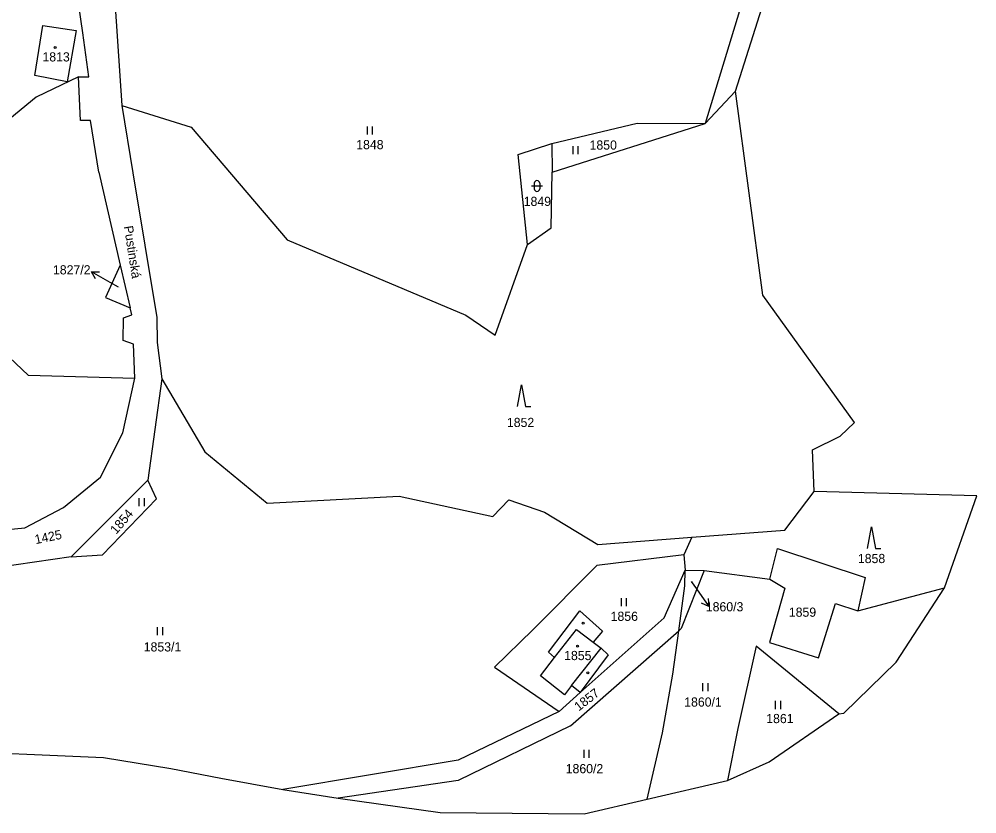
# Model space of a CAD drawing. Extents: x -670359 to -668019, y -978807 to -976674.
# Drawn here: x -668901.2 to -668723.8, y -978807.1 to -978659.9 of the extents above; entities that cross this region are included whole.
import ezdxf

# ---------------------------------------------------------------- set-up
doc = ezdxf.new("R2010")
doc.units = 0
for name, color, linetype in [('Hranice kat_území', 7, 'Continuous'), ('Hranice parcel', 7, 'Continuous'), ('Parcelní čísla', 7, 'Continuous'), ('Pop  PČ popisy', 7, 'Continuous'), ('Vnitřní kresba', 7, 'Continuous'), ('Značky budov', 7, 'Continuous'), ('Značky kultur', 7, 'Continuous')]:
    doc.layers.add(name, color=color, linetype=linetype)

msp = doc.modelspace()

# ---------------------------------------------------------------- linework, layer by layer
at = {"layer": 'Hranice kat_území'}
for points in [[(-668768.5, -978673.25), (-668761.14, -978650.02)], [(-668763.39, -978711.01), (-668768.5, -978673.25)], [(-668746.43, -978734.59), (-668763.39, -978711.01)], [(-668749.12, -978737.1), (-668746.43, -978734.59)], [(-668754.21, -978739.65), (-668749.12, -978737.1)], [(-668753.94, -978747.34), (-668754.21, -978739.65)], [(-668723.78, -978748.19), (-668753.94, -978747.34)], [(-668729.78, -978765.21), (-668723.78, -978748.19)], [(-668738.74, -978778.99), (-668729.78, -978765.21)], [(-668748.42, -978788.44), (-668738.74, -978778.99)], [(-668762.25, -978797.43), (-668749.37, -978788.54)], [(-668749.37, -978788.54), (-668748.42, -978788.44)], [(-668916.93, -978795.26), (-668885.55, -978796.6)], [(-668885.55, -978796.6), (-668873.05, -978798.68)], [(-668769.99, -978800.89), (-668762.25, -978797.43)], [(-668873.05, -978798.68), (-668863.83, -978800.48)], [(-668863.83, -978800.48), (-668852.3, -978802.56)], [(-668784.84, -978804.34), (-668769.99, -978800.89)], [(-668852.3, -978802.56), (-668842.08, -978804.18)], [(-668842.08, -978804.18), (-668823.16, -978806.83)], [(-668796.51, -978807.06), (-668784.84, -978804.34)], [(-668823.16, -978806.83), (-668796.51, -978807.06)]]:
    msp.add_lwpolyline(points, dxfattribs=at)
at = {"layer": 'Hranice parcel'}
for points in [[(-668765.31, -978650.35), (-668774.13, -978679.23)], [(-668889.34, -978662.4), (-668890.13, -978657.34)], [(-668883.41, -978657.54), (-668882.13, -978675.88)], [(-668898.28, -978670.32), (-668896.76, -978661.07)], [(-668896.76, -978661.07), (-668890.61, -978661.98)], [(-668890.61, -978661.98), (-668892.3, -978671.47)], [(-668888.28, -978670.58), (-668889.34, -978662.4)], [(-668892.3, -978671.47), (-668898.28, -978670.32)], [(-668890.2, -978670.54), (-668898.03, -978674.32)], [(-668889.78, -978678.63), (-668890.2, -978670.54)], [(-668890.2, -978670.54), (-668888.28, -978670.58)], [(-668774.13, -978679.23), (-668768.5, -978673.25)], [(-668898.03, -978674.32), (-668902.9, -978678.32)], [(-668882.13, -978675.88), (-668880.1, -978688.32)], [(-668882.13, -978675.88), (-668869.31, -978679.87)], [(-668887.94, -978678.66), (-668889.78, -978678.63)], [(-668886.42, -978688.21), (-668887.94, -978678.66)], [(-668869.31, -978679.87), (-668851.5, -978700.74)], [(-668802.53, -978682.89), (-668786.7, -978679.17)], [(-668802.46, -978688.25), (-668774.13, -978679.23)], [(-668786.7, -978679.17), (-668774.13, -978679.23)], [(-668808.73, -978684.94), (-668802.53, -978682.89)], [(-668802.53, -978682.89), (-668802.46, -978688.25)], [(-668807.01, -978701.61), (-668808.73, -978684.94)], [(-668886.42, -978688.21), (-668882.43, -978705.47)], [(-668880.1, -978688.32), (-668875.68, -978715.11)], [(-668802.64, -978698.56), (-668802.46, -978688.25)], [(-668807.01, -978701.61), (-668802.64, -978698.56)], [(-668851.5, -978700.74), (-668818.45, -978714.68)], [(-668812.99, -978718.38), (-668807.01, -978701.61)], [(-668882.43, -978705.47), (-668885.16, -978711.44)], [(-668882.43, -978705.47), (-668880.61, -978713.36)], [(-668913.58, -978712.53), (-668899.48, -978725.81)], [(-668885.16, -978711.44), (-668880.61, -978713.36)], [(-668881.85, -978715.17), (-668880.32, -978714.63)], [(-668880.32, -978714.63), (-668880.61, -978713.36)], [(-668881.92, -978719.4), (-668881.85, -978715.17)], [(-668875.68, -978715.11), (-668875.6, -978719.76)], [(-668818.45, -978714.68), (-668812.99, -978718.38)], [(-668880.01, -978720.08), (-668881.92, -978719.4)], [(-668875.6, -978719.76), (-668874.76, -978726.49)], [(-668879.72, -978726.4), (-668880.01, -978720.08)], [(-668899.48, -978725.81), (-668879.72, -978726.4)], [(-668881.98, -978736.52), (-668879.72, -978726.4)], [(-668874.76, -978726.49), (-668877.32, -978745.25)], [(-668874.76, -978726.49), (-668866.75, -978739.99)], [(-668886.12, -978744.69), (-668881.98, -978736.52)], [(-668866.75, -978739.99), (-668855.23, -978749.55)], [(-668892.94, -978750.33), (-668886.12, -978744.69)], [(-668877.32, -978745.25), (-668891.55, -978759.47)], [(-668875.7, -978748.71), (-668877.32, -978745.25)], [(-668855.23, -978749.55), (-668830.79, -978748.22)], [(-668830.79, -978748.22), (-668813.41, -978751.97)], [(-668759.34, -978754.52), (-668753.94, -978747.34)], [(-668885.73, -978759.09), (-668875.7, -978748.71)], [(-668813.41, -978751.97), (-668810.47, -978748.9)], [(-668810.47, -978748.9), (-668803.87, -978751.18)], [(-668900.13, -978754.12), (-668892.94, -978750.33)], [(-668803.87, -978751.18), (-668793.97, -978757.19)], [(-668912.88, -978755.34), (-668900.13, -978754.12)], [(-668776.58, -978755.82), (-668759.34, -978754.52)], [(-668793.97, -978757.19), (-668776.58, -978755.82)], [(-668776.58, -978755.82), (-668778.07, -978759.07)], [(-668762.14, -978763.59), (-668760.68, -978757.94)], [(-668760.68, -978757.94), (-668744.45, -978763.26)], [(-668891.55, -978759.47), (-668911.96, -978762.42)], [(-668891.55, -978759.47), (-668885.73, -978759.09)], [(-668778.07, -978759.07), (-668794.16, -978761.07)], [(-668778.07, -978759.07), (-668777.8, -978761.96)], [(-668794.16, -978761.07), (-668806.03, -978773)], [(-668781.72, -978770.77), (-668777.8, -978761.96)], [(-668779, -978773.14), (-668777.88, -978764.85), (-668777.8, -978761.96)], [(-668774.28, -978762.02), (-668778.55, -978772.74), (-668779, -978773.14)], [(-668777.8, -978761.96), (-668774.28, -978762.02)], [(-668774.28, -978762.02), (-668762.14, -978763.59)], [(-668762.14, -978763.59), (-668759.37, -978765.24)], [(-668744.45, -978763.26), (-668745.84, -978769.48)], [(-668759.37, -978765.24), (-668762.19, -978775.35)], [(-668745.84, -978769.48), (-668729.78, -978765.21)], [(-668803.12, -978777.11), (-668797.3, -978769.45)], [(-668797.3, -978769.45), (-668793.12, -978773.21)], [(-668753.11, -978778.15), (-668749.99, -978768.1)], [(-668749.99, -978768.1), (-668745.84, -978769.48)], [(-668781.72, -978770.77), (-668797.24, -978784.57)], [(-668806.03, -978773), (-668813.13, -978779.89)], [(-668799.03, -978790.78), (-668779, -978773.14)], [(-668780.09, -978781.19), (-668779, -978773.14)], [(-668793.12, -978773.21), (-668794.84, -978775.26)], [(-668794.84, -978775.26), (-668793.34, -978776.4)], [(-668793.34, -978776.4), (-668792.04, -978777.62)], [(-668764.68, -978776.03), (-668768.06, -978791.25)], [(-668749.37, -978788.54), (-668764.68, -978776.03)], [(-668762.19, -978775.35), (-668753.11, -978778.15)], [(-668804.63, -978781.48), (-668802.01, -978778.09)], [(-668802.01, -978778.09), (-668803.12, -978777.11)], [(-668792.04, -978777.62), (-668797.24, -978784.57)], [(-668813.13, -978779.89), (-668801.15, -978788.1)], [(-668800.13, -978785), (-668804.63, -978781.48)], [(-668781.98, -978792.03), (-668780.09, -978781.19)], [(-668798.86, -978783.3), (-668800.13, -978785)], [(-668797.24, -978784.57), (-668798.86, -978783.3)], [(-668801.15, -978788.1), (-668797.24, -978784.57)], [(-668801.15, -978788.1), (-668819.87, -978797.13)], [(-668799.03, -978790.78), (-668819.86, -978800.89)], [(-668784.84, -978804.34), (-668781.98, -978792.03)], [(-668768.06, -978791.25), (-668769.99, -978800.89)], [(-668819.87, -978797.13), (-668852.3, -978802.56)], [(-668819.86, -978800.89), (-668842.08, -978804.18)]]:
    msp.add_lwpolyline(points, dxfattribs=at)
at = {"layer": 'Parcelní čísla'}
for p, q in [((-668887.01, -978707.96), (-668887.77, -978706.66)), ((-668882.75, -978709.52), (-668884.29, -978708.64)), ((-668776.68, -978764.03), (-668775.71, -978765.41)), ((-668773.54, -978767.18), (-668773.41, -978768.68))]:
    msp.add_line(p, q, dxfattribs=at)
for points in [[(-668884.29, -978708.64), (-668887.77, -978706.66), (-668886.27, -978706.65)], [(-668775.71, -978765.41), (-668773.41, -978768.68), (-668774.77, -978768.05)]]:
    msp.add_lwpolyline(points, dxfattribs=at)
at = {"layer": 'Vnitřní kresba'}
for points in [[(-668802.01, -978778.09), (-668797.95, -978772.9)], [(-668797.95, -978772.9), (-668794.84, -978775.26)], [(-668798.86, -978783.3), (-668793.34, -978776.4)]]:
    msp.add_lwpolyline(points, dxfattribs=at)
at = {"layer": 'Značky budov'}
for centre in [(-668894.49, -978665.12), (-668797.72, -978775.99)]:
    msp.add_circle(centre, 0.175, dxfattribs=at)
at = {"layer": 'Značky kultur'}
for p, q in [((-668836.73, -978679.77), (-668836.73, -978681.27)), ((-668835.73, -978681.27), (-668835.73, -978679.77)), ((-668798.61, -978683.4), (-668798.61, -978684.9)), ((-668797.61, -978684.9), (-668797.61, -978683.4)), ((-668806.25, -978690.78), (-668804.25, -978690.78)), ((-668805.75, -978690.28), (-668805.75, -978691.28)), ((-668804.75, -978690.28), (-668804.75, -978691.28)), ((-668878.97, -978748.6), (-668878.97, -978750.1)), ((-668877.97, -978750.1), (-668877.97, -978748.6)), ((-668789.65, -978767.12), (-668789.65, -978768.62)), ((-668788.65, -978768.62), (-668788.65, -978767.12)), ((-668875.58, -978772.47), (-668875.58, -978773.97)), ((-668874.58, -978773.97), (-668874.58, -978772.47)), ((-668774.57, -978782.84), (-668774.57, -978784.34)), ((-668773.57, -978784.34), (-668773.57, -978782.84)), ((-668761.11, -978786.16), (-668761.11, -978787.66)), ((-668760.11, -978787.66), (-668760.11, -978786.16)), ((-668796.57, -978795.18), (-668796.57, -978796.68)), ((-668795.57, -978796.68), (-668795.57, -978795.18))]:
    msp.add_line(p, q, dxfattribs=at)
for points in [[(-668808.89, -978731.63), (-668808.14, -978727.63), (-668807.39, -978731.63), (-668806.39, -978731.63)], [(-668744.06, -978757.92), (-668743.31, -978753.92), (-668742.56, -978757.92), (-668741.56, -978757.92)]]:
    msp.add_lwpolyline(points, dxfattribs=at)
for centre in [(-668894.49, -978665.12), (-668796.69, -978771.73), (-668797.72, -978775.99), (-668795.85, -978780.94)]:
    msp.add_circle(centre, 0.175, dxfattribs=at)
for centre, start, end in [((-668805.25, -978690.28), 0, 180), ((-668805.25, -978691.28), 180, 0)]:
    msp.add_arc(centre, 0.5, start, end, dxfattribs=at)

# ---------------------------------------------------------------- texts
at = {"layer": 'Parcelní čísla'}
for s, height, p in [('1813', 1.7, (-668896.85, -978667.72)), ('1848', 1.7, (-668838.73, -978683.97)), ('1850', 1.7, (-668795.51, -978684.05)), ('1849', 1.7, (-668807.71, -978694.48)), ('1827/2', 1.7, (-668894.9, -978707.16)), ('1827/2', 0.1, (-668882.75, -978709.52)), ('1852', 1.7, (-668810.82, -978735.42)), ('1858', 1.7, (-668745.81, -978760.62)), ('1860/3', 0.1, (-668776.68, -978764.03)), ('1860/3', 1.7, (-668773.98, -978769.56)), ('1856', 1.7, (-668791.61, -978771.32)), ('1859', 1.7, (-668758.6, -978770.56)), ('1853/1', 1.7, (-668878.09, -978776.99)), ('1855', 1.7, (-668800.22, -978778.59)), ('1860/1', 1.7, (-668777.98, -978787.2)), ('1861', 1.7, (-668762.79, -978790.26)), ('1860/2', 1.7, (-668799.93, -978799.54))]:
    msp.add_text(s, height=height, dxfattribs=at).set_placement(p)
for s, rotation, p in [('1854', 49.5378, (-668883.19, -978755.4)), ('1425', 11.707, (-668898.09, -978757.12)), ('1857', 37.7389, (-668797.52, -978788.12))]:
    msp.add_text(s, height=1.7, rotation=rotation, dxfattribs=at).set_placement(p)
at = {"layer": 'Pop  PČ popisy'}
msp.add_text('Pustinská', height=1.7, rotation=278.8665, dxfattribs=at).set_placement((-668881.78, -978698.27))

doc.saveas('drawing.dxf')
